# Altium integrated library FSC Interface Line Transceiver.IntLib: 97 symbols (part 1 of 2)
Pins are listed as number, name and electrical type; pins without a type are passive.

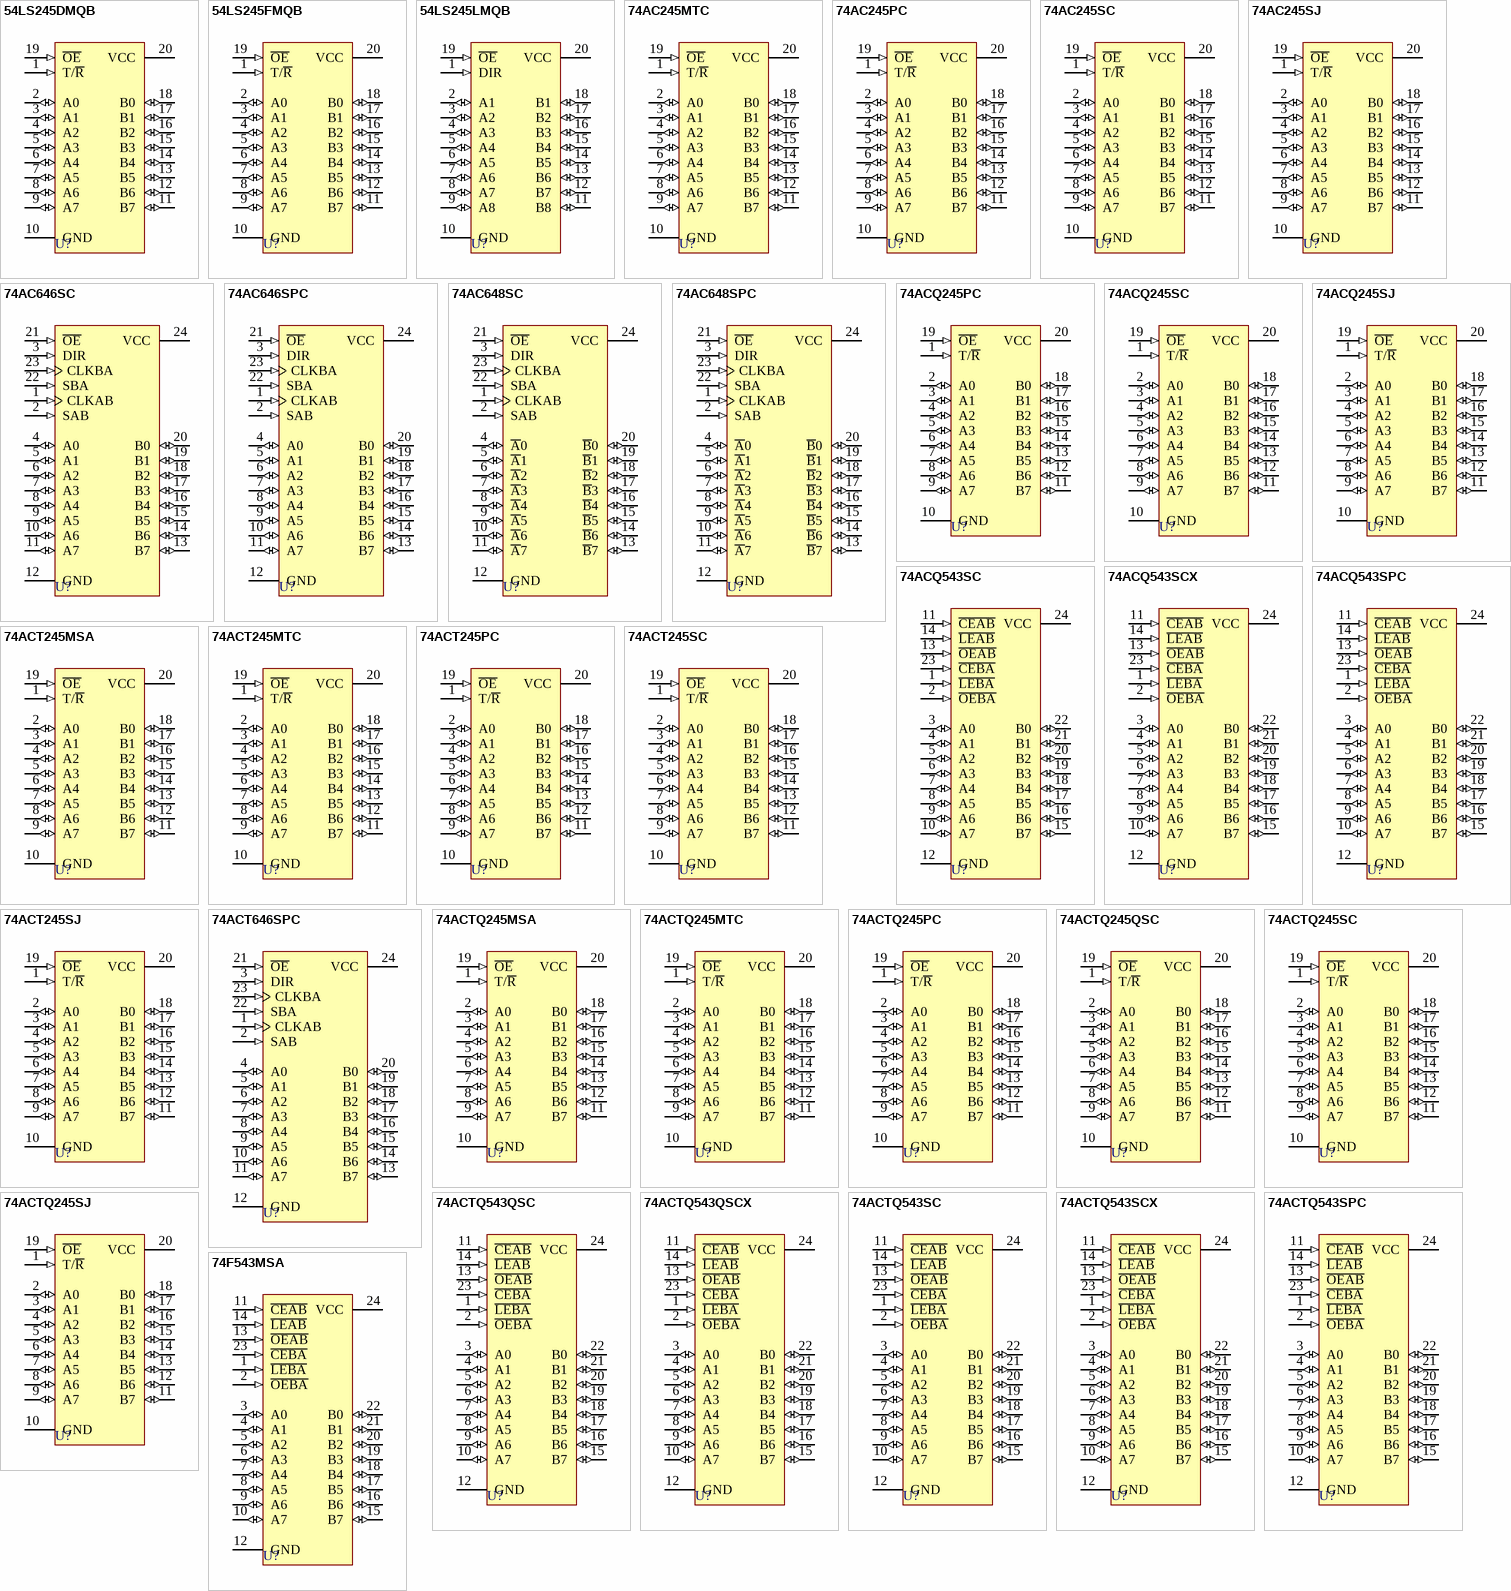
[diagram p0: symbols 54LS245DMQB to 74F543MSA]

## 54LS245DMQB
designator U?
3-State Octal Bus Transceiver
footprint J20A (DIP; 20 Leads; Row Spacing 7.62 mm; Pitch 2.54 mm)
3D model J20A (DIP; 20 Leads; Row Spacing 7.62 mm; Pitch 2.54 mm)
simulation model 74F245 (SIMCODE)
signal-integrity model 54LS245DMQB
pins: 1 T/~{R} (in), 2 A0 (io), 3 A1 (io), 4 A2 (io), 5 A3 (io), 6 A4 (io), 7 A5 (io), 8 A6 (io), 9 A7 (io), 10 GND (power), 11 B7 (io), 12 B6 (io), 13 B5 (io), 14 B4 (io), 15 B3 (io), 16 B2 (io), 17 B1 (io), 18 B0 (io), 19 ~{OE} (in), 20 VCC (power)

## 54LS245FMQB
designator U?
3-State Octal Bus Transceiver
footprint W20A (DFP; 20 Leads; Body 13.7 x 7.2 mm (LxW max); Pitch 1.27 mm)
3D model W20A (DFP; 20 Leads; Body 13.7 x 7.2 mm (LxW max); Pitch 1.27 mm)
simulation model 74F245 (SIMCODE)
signal-integrity model 54LS245FMQB
pins: 1 T/~{R} (in), 2 A0 (io), 3 A1 (io), 4 A2 (io), 5 A3 (io), 6 A4 (io), 7 A5 (io), 8 A6 (io), 9 A7 (io), 10 GND (power), 11 B7 (io), 12 B6 (io), 13 B5 (io), 14 B4 (io), 15 B3 (io), 16 B2 (io), 17 B1 (io), 18 B0 (io), 19 ~{OE} (in), 20 VCC (power)

## 54LS245LMQB
designator U?
3-State Octal Bus Transceiver
footprint E20A (Leadless Chip Carrier; 20 Terminals; Body 8.9 x 8.9 mm)
simulation model 74F245 (SIMCODE)
signal-integrity model 54LS245LMQB
pins: 1 DIR (in), 2 A1 (io), 3 A2 (io), 4 A3 (io), 5 A4 (io), 6 A5 (io), 7 A6 (io), 8 A7 (io), 9 A8 (io), 10 GND (power), 11 B8 (io), 12 B7 (io), 13 B6 (io), 14 B5 (io), 15 B4 (io), 16 B3 (io), 17 B2 (io), 18 B1 (io), 19 ~{OE} (in), 20 VCC (power)

## 74AC245MTC
designator U?
Octal Bidirectional Transceiver with 3-State Input/Output
footprint MTC20 (Shrink Small Outline; 20 Leads; Body Width 4.4 mm; Pitch 0.65 mm)
3D model MTC20 (Shrink Small Outline; 20 Leads; Body Width 4.4 mm; Pitch 0.65 mm)
simulation model 74F245 (SIMCODE)
signal-integrity model 74AC245MTC
pins: 1 T/~{R} (in), 2 A0 (io), 3 A1 (io), 4 A2 (io), 5 A3 (io), 6 A4 (io), 7 A5 (io), 8 A6 (io), 9 A7 (io), 10 GND (power), 11 B7 (io), 12 B6 (io), 13 B5 (io), 14 B4 (io), 15 B3 (io), 16 B2 (io), 17 B1 (io), 18 B0 (io), 19 ~{OE} (in), 20 VCC (power)

## 74AC245PC
designator U?
Octal Bidirectional Transceiver with 3-State Input/Output
footprint N20A (DIP; 20 Leads; Row Spacing 7.62 mm; Pitch 2.54 mm)
3D model N20A (DIP; 20 Leads; Row Spacing 7.62 mm; Pitch 2.54 mm)
simulation model 74F245 (SIMCODE)
signal-integrity model 74AC245PC
pins: 1 T/~{R} (in), 2 A0 (io), 3 A1 (io), 4 A2 (io), 5 A3 (io), 6 A4 (io), 7 A5 (io), 8 A6 (io), 9 A7 (io), 10 GND (power), 11 B7 (io), 12 B6 (io), 13 B5 (io), 14 B4 (io), 15 B3 (io), 16 B2 (io), 17 B1 (io), 18 B0 (io), 19 ~{OE} (in), 20 VCC (power)

## 74AC245SC
designator U?
Octal Bidirectional Transceiver with 3-State Input/Output
footprint M20B_N (SOIC, 20-Leads, Body 12.8x7.5mm, Pitch 1.27mm, IPC Medium Density)
footprint M20B_L (SOIC, 20-Leads, Body 12.8x7.5mm, Pitch 1.27mm, IPC High Density)
footprint M20B_M (SOIC, 20-Leads, Body 12.8x7.5mm, Pitch 1.27mm, IPC Low Density)
3D model M20B (20-Pin Small Outline Integrated Circuit 1.27 mm Pitch)
simulation model 74F245 (SIMCODE)
signal-integrity model 74AC245SC
pins: 1 T/~{R} (in), 2 A0 (io), 3 A1 (io), 4 A2 (io), 5 A3 (io), 6 A4 (io), 7 A5 (io), 8 A6 (io), 9 A7 (io), 10 GND (power), 11 B7 (io), 12 B6 (io), 13 B5 (io), 14 B4 (io), 15 B3 (io), 16 B2 (io), 17 B1 (io), 18 B0 (io), 19 ~{OE} (in), 20 VCC (power)

## 74AC245SJ
designator U?
Octal Bidirectional Transceiver with 3-State Input/Output
footprint M20D_N (SOP, 20-Leads, Body 12.6x5.3mm, Pitch 1.27mm, IPC Medium Density)
footprint M20D_L (SOP, 20-Leads, Body 12.6x5.3mm, Pitch 1.27mm, IPC High Density)
footprint M20D_M (SOP, 20-Leads, Body 12.6x5.3mm, Pitch 1.27mm, IPC Low Density)
3D model M20D (20-Pin Small Outline Package 1.27 mm Pitch)
simulation model 74F245 (SIMCODE)
signal-integrity model 74AC245SJ
pins: 1 T/~{R} (in), 2 A0 (io), 3 A1 (io), 4 A2 (io), 5 A3 (io), 6 A4 (io), 7 A5 (io), 8 A6 (io), 9 A7 (io), 10 GND (power), 11 B7 (io), 12 B6 (io), 13 B5 (io), 14 B4 (io), 15 B3 (io), 16 B2 (io), 17 B1 (io), 18 B0 (io), 19 ~{OE} (in), 20 VCC (power)

## 74AC646SC
designator U?
Octal Transceiver/Register with 3-State Output
footprint M24B_N (SOIC, 24-Leads, Body 15.4x7.5mm, Pitch 1.27mm, IPC Medium Density)
footprint M24B_L (SOIC, 24-Leads, Body 15.4x7.5mm, Pitch 1.27mm, IPC High Density)
footprint M24B_M (SOIC, 24-Leads, Body 15.4x7.5mm, Pitch 1.27mm, IPC Low Density)
3D model M24B (24-Pin Small Outline Integrated Circuit 1.27 mm Pitch)
signal-integrity model 74AC646SC
pins: 1 CLKAB (in), 2 SAB (in), 3 DIR (in), 4 A0 (io), 5 A1 (io), 6 A2 (io), 7 A3 (io), 8 A4 (io), 9 A5 (io), 10 A6 (io), 11 A7 (io), 12 GND (power), 13 B7 (io), 14 B6 (io), 15 B5 (io), 16 B4 (io), 17 B3 (io), 18 B2 (io), 19 B1 (io), 20 B0 (io), 21 ~{OE} (in), 22 SBA (in), 23 CLKBA (in), 24 VCC (power)

## 74AC646SPC
designator U?
Octal Transceiver/Register with 3-State Output
footprint N24C (DIP; 24 Leads; Row Spacing 7.62 mm; Pitch 2.54 mm)
3D model N24C (DIP; 24 Leads; Row Spacing 7.62 mm; Pitch 2.54 mm)
signal-integrity model 74AC646SPC
pins: 1 CLKAB (in), 2 SAB (in), 3 DIR (in), 4 A0 (io), 5 A1 (io), 6 A2 (io), 7 A3 (io), 8 A4 (io), 9 A5 (io), 10 A6 (io), 11 A7 (io), 12 GND (power), 13 B7 (io), 14 B6 (io), 15 B5 (io), 16 B4 (io), 17 B3 (io), 18 B2 (io), 19 B1 (io), 20 B0 (io), 21 ~{OE} (in), 22 SBA (in), 23 CLKBA (in), 24 VCC (power)

## 74AC648SC
designator U?
Octal Transceiver/Register with 3-State Output
footprint M24B_N (SOIC, 24-Leads, Body 15.4x7.5mm, Pitch 1.27mm, IPC Medium Density)
footprint M24B_L (SOIC, 24-Leads, Body 15.4x7.5mm, Pitch 1.27mm, IPC High Density)
footprint M24B_M (SOIC, 24-Leads, Body 15.4x7.5mm, Pitch 1.27mm, IPC Low Density)
3D model M24B (24-Pin Small Outline Integrated Circuit 1.27 mm Pitch)
signal-integrity model 74AC648SC
pins: 1 CLKAB (in), 2 SAB (in), 3 DIR (in), 4 ~{A}0 (io), 5 ~{A}1 (io), 6 ~{A}2 (io), 7 ~{A}3 (io), 8 ~{A}4 (io), 9 ~{A}5 (io), 10 ~{A}6 (io), 11 ~{A}7 (io), 12 GND (power), 13 ~{B}7 (io), 14 ~{B}6 (io), 15 ~{B}5 (io), 16 ~{B}4 (io), 17 ~{B}3 (io), 18 ~{B}2 (io), 19 ~{B}1 (io), 20 ~{B}0 (io), 21 ~{OE} (in), 22 SBA (in), 23 CLKBA (in), 24 VCC (power)

## 74AC648SPC
designator U?
Octal Transceiver/Register with 3-State Output
footprint N24C (DIP; 24 Leads; Row Spacing 7.62 mm; Pitch 2.54 mm)
3D model N24C (DIP; 24 Leads; Row Spacing 7.62 mm; Pitch 2.54 mm)
signal-integrity model 74AC648SPC
pins: 1 CLKAB (in), 2 SAB (in), 3 DIR (in), 4 ~{A}0 (io), 5 ~{A}1 (io), 6 ~{A}2 (io), 7 ~{A}3 (io), 8 ~{A}4 (io), 9 ~{A}5 (io), 10 ~{A}6 (io), 11 ~{A}7 (io), 12 GND (power), 13 ~{B}7 (io), 14 ~{B}6 (io), 15 ~{B}5 (io), 16 ~{B}4 (io), 17 ~{B}3 (io), 18 ~{B}2 (io), 19 ~{B}1 (io), 20 ~{B}0 (io), 21 ~{OE} (in), 22 SBA (in), 23 CLKBA (in), 24 VCC (power)

## 74ACQ245PC
designator U?
Octal Bidirectional Transceiver with 3-State Input/Output
footprint N20A (DIP; 20 Leads; Row Spacing 7.62 mm; Pitch 2.54 mm)
3D model N20A (DIP; 20 Leads; Row Spacing 7.62 mm; Pitch 2.54 mm)
simulation model 74F245 (SIMCODE)
pins: 1 T/~{R} (in), 2 A0 (io), 3 A1 (io), 4 A2 (io), 5 A3 (io), 6 A4 (io), 7 A5 (io), 8 A6 (io), 9 A7 (io), 10 GND (power), 11 B7 (io), 12 B6 (io), 13 B5 (io), 14 B4 (io), 15 B3 (io), 16 B2 (io), 17 B1 (io), 18 B0 (io), 19 ~{OE} (in), 20 VCC (power)

## 74ACQ245SC
designator U?
Octal Bidirectional Transceiver with 3-State Input/Output
footprint M20B_N (SOIC, 20-Leads, Body 12.8x7.5mm, Pitch 1.27mm, IPC Medium Density)
footprint M20B_L (SOIC, 20-Leads, Body 12.8x7.5mm, Pitch 1.27mm, IPC High Density)
footprint M20B_M (SOIC, 20-Leads, Body 12.8x7.5mm, Pitch 1.27mm, IPC Low Density)
3D model M20B (20-Pin Small Outline Integrated Circuit 1.27 mm Pitch)
simulation model 74F245 (SIMCODE)
pins: 1 T/~{R} (in), 2 A0 (io), 3 A1 (io), 4 A2 (io), 5 A3 (io), 6 A4 (io), 7 A5 (io), 8 A6 (io), 9 A7 (io), 10 GND (power), 11 B7 (io), 12 B6 (io), 13 B5 (io), 14 B4 (io), 15 B3 (io), 16 B2 (io), 17 B1 (io), 18 B0 (io), 19 ~{OE} (in), 20 VCC (power)

## 74ACQ245SJ
designator U?
Octal Bidirectional Transceiver with 3-State Input/Output
footprint M20D_N (SOP, 20-Leads, Body 12.6x5.3mm, Pitch 1.27mm, IPC Medium Density)
footprint M20D_L (SOP, 20-Leads, Body 12.6x5.3mm, Pitch 1.27mm, IPC High Density)
footprint M20D_M (SOP, 20-Leads, Body 12.6x5.3mm, Pitch 1.27mm, IPC Low Density)
3D model M20D (20-Pin Small Outline Package 1.27 mm Pitch)
simulation model 74F245 (SIMCODE)
pins: 1 T/~{R} (in), 2 A0 (io), 3 A1 (io), 4 A2 (io), 5 A3 (io), 6 A4 (io), 7 A5 (io), 8 A6 (io), 9 A7 (io), 10 GND (power), 11 B7 (io), 12 B6 (io), 13 B5 (io), 14 B4 (io), 15 B3 (io), 16 B2 (io), 17 B1 (io), 18 B0 (io), 19 ~{OE} (in), 20 VCC (power)

## 74ACQ543SC
designator U?
Octal Registered Transceiver with Tri-State Output
footprint M24B_N (SOIC, 24-Leads, Body 15.4x7.5mm, Pitch 1.27mm, IPC Medium Density)
footprint M24B_L (SOIC, 24-Leads, Body 15.4x7.5mm, Pitch 1.27mm, IPC High Density)
footprint M24B_M (SOIC, 24-Leads, Body 15.4x7.5mm, Pitch 1.27mm, IPC Low Density)
3D model M24B (24-Pin Small Outline Integrated Circuit 1.27 mm Pitch)
pins: 1 ~{LEBA} (in), 2 ~{OEBA} (in), 3 A0 (io), 4 A1 (io), 5 A2 (io), 6 A3 (io), 7 A4 (io), 8 A5 (io), 9 A6 (io), 10 A7 (io), 11 ~{CEAB} (in), 12 GND (power), 13 ~{OEAB} (in), 14 ~{LEAB} (in), 15 B7 (io), 16 B6 (io), 17 B5 (io), 18 B4 (io), 19 B3 (io), 20 B2 (io), 21 B1 (io), 22 B0 (io), 23 ~{CEBA} (in), 24 VCC (power)

## 74ACQ543SCX
designator U?
Octal Registered Transceiver with Tri-State Output
footprint M24B_N (SOIC, 24-Leads, Body 15.4x7.5mm, Pitch 1.27mm, IPC Medium Density)
footprint M24B_L (SOIC, 24-Leads, Body 15.4x7.5mm, Pitch 1.27mm, IPC High Density)
footprint M24B_M (SOIC, 24-Leads, Body 15.4x7.5mm, Pitch 1.27mm, IPC Low Density)
3D model M24B (24-Pin Small Outline Integrated Circuit 1.27 mm Pitch)
pins: 1 ~{LEBA} (in), 2 ~{OEBA} (in), 3 A0 (io), 4 A1 (io), 5 A2 (io), 6 A3 (io), 7 A4 (io), 8 A5 (io), 9 A6 (io), 10 A7 (io), 11 ~{CEAB} (in), 12 GND (power), 13 ~{OEAB} (in), 14 ~{LEAB} (in), 15 B7 (io), 16 B6 (io), 17 B5 (io), 18 B4 (io), 19 B3 (io), 20 B2 (io), 21 B1 (io), 22 B0 (io), 23 ~{CEBA} (in), 24 VCC (power)

## 74ACQ543SPC
designator U?
Octal Registered Transceiver with Tri-State Output
footprint N24C (DIP; 24 Leads; Row Spacing 7.62 mm; Pitch 2.54 mm)
3D model N24C (DIP; 24 Leads; Row Spacing 7.62 mm; Pitch 2.54 mm)
pins: 1 ~{LEBA} (in), 2 ~{OEBA} (in), 3 A0 (io), 4 A1 (io), 5 A2 (io), 6 A3 (io), 7 A4 (io), 8 A5 (io), 9 A6 (io), 10 A7 (io), 11 ~{CEAB} (in), 12 GND (power), 13 ~{OEAB} (in), 14 ~{LEAB} (in), 15 B7 (io), 16 B6 (io), 17 B5 (io), 18 B4 (io), 19 B3 (io), 20 B2 (io), 21 B1 (io), 22 B0 (io), 23 ~{CEBA} (in), 24 VCC (power)

## 74ACT245MSA
designator U?
Octal Bidirectional Transceiver with 3-State Input/Output
footprint MSA20 (SSOP; 20 Leads; Body Width 5.3 mm; Pitch 0.65 mm)
3D model MSA20 (SSOP; 20 Leads; Body Width 5.3 mm; Pitch 0.65 mm)
simulation model 74F245 (SIMCODE)
signal-integrity model 74ACT245MSA
pins: 1 T/~{R} (in), 2 A0 (io), 3 A1 (io), 4 A2 (io), 5 A3 (io), 6 A4 (io), 7 A5 (io), 8 A6 (io), 9 A7 (io), 10 GND (power), 11 B7 (io), 12 B6 (io), 13 B5 (io), 14 B4 (io), 15 B3 (io), 16 B2 (io), 17 B1 (io), 18 B0 (io), 19 ~{OE} (in), 20 VCC (power)

## 74ACT245MTC
designator U?
Octal Bidirectional Transceiver with 3-State Input/Output
footprint MTC20 (Shrink Small Outline; 20 Leads; Body Width 4.4 mm; Pitch 0.65 mm)
3D model MTC20 (Shrink Small Outline; 20 Leads; Body Width 4.4 mm; Pitch 0.65 mm)
simulation model 74F245 (SIMCODE)
signal-integrity model 74ACT245MTC
pins: 1 T/~{R} (in), 2 A0 (io), 3 A1 (io), 4 A2 (io), 5 A3 (io), 6 A4 (io), 7 A5 (io), 8 A6 (io), 9 A7 (io), 10 GND (power), 11 B7 (io), 12 B6 (io), 13 B5 (io), 14 B4 (io), 15 B3 (io), 16 B2 (io), 17 B1 (io), 18 B0 (io), 19 ~{OE} (in), 20 VCC (power)

## 74ACT245PC
designator U?
Octal Bidirectional Transceiver with 3-State Input/Output
footprint N20A (DIP; 20 Leads; Row Spacing 7.62 mm; Pitch 2.54 mm)
3D model N20A (DIP; 20 Leads; Row Spacing 7.62 mm; Pitch 2.54 mm)
simulation model 74F245 (SIMCODE)
signal-integrity model 74ACT245PC
pins: 1 T/~{R} (in), 2 A0 (io), 3 A1 (io), 4 A2 (io), 5 A3 (io), 6 A4 (io), 7 A5 (io), 8 A6 (io), 9 A7 (io), 10 GND (power), 11 B7 (io), 12 B6 (io), 13 B5 (io), 14 B4 (io), 15 B3 (io), 16 B2 (io), 17 B1 (io), 18 B0 (io), 19 ~{OE} (in), 20 VCC (power)

## 74ACT245SC
designator U?
Octal Bidirectional Transceiver with 3-State Input/Output
footprint M20B_N (SOIC, 20-Leads, Body 12.8x7.5mm, Pitch 1.27mm, IPC Medium Density)
footprint M20B_L (SOIC, 20-Leads, Body 12.8x7.5mm, Pitch 1.27mm, IPC High Density)
footprint M20B_M (SOIC, 20-Leads, Body 12.8x7.5mm, Pitch 1.27mm, IPC Low Density)
3D model M20B (20-Pin Small Outline Integrated Circuit 1.27 mm Pitch)
simulation model 74F245 (SIMCODE)
signal-integrity model 74ACT245SC
pins: 1 T/~{R} (in), 2 A0 (io), 3 A1 (io), 4 A2 (io), 5 A3 (io), 6 A4 (io), 7 A5 (io), 8 A6 (io), 9 A7 (io), 10 GND (power), 11 B7 (io), 12 B6 (io), 13 B5 (io), 14 B4 (io), 15 B3 (io), 16 B2 (io), 17 B1 (io), 18 B0 (io), 19 ~{OE} (in), 20 VCC (power)

## 74ACT245SJ
designator U?
Octal Bidirectional Transceiver with 3-State Input/Output
footprint M20D_N (SOP, 20-Leads, Body 12.6x5.3mm, Pitch 1.27mm, IPC Medium Density)
footprint M20D_L (SOP, 20-Leads, Body 12.6x5.3mm, Pitch 1.27mm, IPC High Density)
footprint M20D_M (SOP, 20-Leads, Body 12.6x5.3mm, Pitch 1.27mm, IPC Low Density)
3D model M20D (20-Pin Small Outline Package 1.27 mm Pitch)
simulation model 74F245 (SIMCODE)
signal-integrity model 74ACT245SJ
pins: 1 T/~{R} (in), 2 A0 (io), 3 A1 (io), 4 A2 (io), 5 A3 (io), 6 A4 (io), 7 A5 (io), 8 A6 (io), 9 A7 (io), 10 GND (power), 11 B7 (io), 12 B6 (io), 13 B5 (io), 14 B4 (io), 15 B3 (io), 16 B2 (io), 17 B1 (io), 18 B0 (io), 19 ~{OE} (in), 20 VCC (power)

## 74ACT646SPC
designator U?
Octal Transceiver/Register with 3-State Output
footprint N24C (DIP; 24 Leads; Row Spacing 7.62 mm; Pitch 2.54 mm)
3D model N24C (DIP; 24 Leads; Row Spacing 7.62 mm; Pitch 2.54 mm)
signal-integrity model 74ACT646SPC
pins: 1 CLKAB (in), 2 SAB (in), 3 DIR (in), 4 A0 (io), 5 A1 (io), 6 A2 (io), 7 A3 (io), 8 A4 (io), 9 A5 (io), 10 A6 (io), 11 A7 (io), 12 GND (power), 13 B7 (io), 14 B6 (io), 15 B5 (io), 16 B4 (io), 17 B3 (io), 18 B2 (io), 19 B1 (io), 20 B0 (io), 21 ~{OE} (in), 22 SBA (in), 23 CLKBA (in), 24 VCC (power)

## 74ACTQ245MSA
designator U?
Octal Bidirectional Transceiver with 3-State Input/Output
footprint MSA20 (SSOP; 20 Leads; Body Width 5.3 mm; Pitch 0.65 mm)
3D model MSA20 (SSOP; 20 Leads; Body Width 5.3 mm; Pitch 0.65 mm)
simulation model 74F245 (SIMCODE)
pins: 1 T/~{R} (in), 2 A0 (io), 3 A1 (io), 4 A2 (io), 5 A3 (io), 6 A4 (io), 7 A5 (io), 8 A6 (io), 9 A7 (io), 10 GND (power), 11 B7 (io), 12 B6 (io), 13 B5 (io), 14 B4 (io), 15 B3 (io), 16 B2 (io), 17 B1 (io), 18 B0 (io), 19 ~{OE} (in), 20 VCC (power)

## 74ACTQ245MTC
designator U?
Octal Bidirectional Transceiver with 3-State Input/Output
footprint MTC20 (Shrink Small Outline; 20 Leads; Body Width 4.4 mm; Pitch 0.65 mm)
3D model MTC20 (Shrink Small Outline; 20 Leads; Body Width 4.4 mm; Pitch 0.65 mm)
simulation model 74F245 (SIMCODE)
pins: 1 T/~{R} (in), 2 A0 (io), 3 A1 (io), 4 A2 (io), 5 A3 (io), 6 A4 (io), 7 A5 (io), 8 A6 (io), 9 A7 (io), 10 GND (power), 11 B7 (io), 12 B6 (io), 13 B5 (io), 14 B4 (io), 15 B3 (io), 16 B2 (io), 17 B1 (io), 18 B0 (io), 19 ~{OE} (in), 20 VCC (power)

## 74ACTQ245PC
designator U?
Octal Bidirectional Transceiver with 3-State Input/Output
footprint N20A (DIP; 20 Leads; Row Spacing 7.62 mm; Pitch 2.54 mm)
3D model N20A (DIP; 20 Leads; Row Spacing 7.62 mm; Pitch 2.54 mm)
simulation model 74F245 (SIMCODE)
pins: 1 T/~{R} (in), 2 A0 (io), 3 A1 (io), 4 A2 (io), 5 A3 (io), 6 A4 (io), 7 A5 (io), 8 A6 (io), 9 A7 (io), 10 GND (power), 11 B7 (io), 12 B6 (io), 13 B5 (io), 14 B4 (io), 15 B3 (io), 16 B2 (io), 17 B1 (io), 18 B0 (io), 19 ~{OE} (in), 20 VCC (power)

## 74ACTQ245QSC
designator U?
Octal Bidirectional Transceiver with 3-State Input/Output
footprint MQA20 (SSOP; 20 Leads; Body Width 3.9 mm; Pitch 0.635 mm)
3D model MQA20 (SSOP; 20 Leads; Body Width 3.9 mm; Pitch 0.635 mm)
simulation model 74F245 (SIMCODE)
pins: 1 T/~{R} (in), 2 A0 (io), 3 A1 (io), 4 A2 (io), 5 A3 (io), 6 A4 (io), 7 A5 (io), 8 A6 (io), 9 A7 (io), 10 GND (power), 11 B7 (io), 12 B6 (io), 13 B5 (io), 14 B4 (io), 15 B3 (io), 16 B2 (io), 17 B1 (io), 18 B0 (io), 19 ~{OE} (in), 20 VCC (power)

## 74ACTQ245SC
designator U?
Octal Bidirectional Transceiver with 3-State Input/Output
footprint M20B_N (SOIC, 20-Leads, Body 12.8x7.5mm, Pitch 1.27mm, IPC Medium Density)
footprint M20B_L (SOIC, 20-Leads, Body 12.8x7.5mm, Pitch 1.27mm, IPC High Density)
footprint M20B_M (SOIC, 20-Leads, Body 12.8x7.5mm, Pitch 1.27mm, IPC Low Density)
3D model M20B (20-Pin Small Outline Integrated Circuit 1.27 mm Pitch)
simulation model 74F245 (SIMCODE)
pins: 1 T/~{R} (in), 2 A0 (io), 3 A1 (io), 4 A2 (io), 5 A3 (io), 6 A4 (io), 7 A5 (io), 8 A6 (io), 9 A7 (io), 10 GND (power), 11 B7 (io), 12 B6 (io), 13 B5 (io), 14 B4 (io), 15 B3 (io), 16 B2 (io), 17 B1 (io), 18 B0 (io), 19 ~{OE} (in), 20 VCC (power)

## 74ACTQ245SJ
designator U?
Octal Bidirectional Transceiver with 3-State Input/Output
footprint M20D_N (SOP, 20-Leads, Body 12.6x5.3mm, Pitch 1.27mm, IPC Medium Density)
footprint M20D_L (SOP, 20-Leads, Body 12.6x5.3mm, Pitch 1.27mm, IPC High Density)
footprint M20D_M (SOP, 20-Leads, Body 12.6x5.3mm, Pitch 1.27mm, IPC Low Density)
3D model M20D (20-Pin Small Outline Package 1.27 mm Pitch)
simulation model 74F245 (SIMCODE)
pins: 1 T/~{R} (in), 2 A0 (io), 3 A1 (io), 4 A2 (io), 5 A3 (io), 6 A4 (io), 7 A5 (io), 8 A6 (io), 9 A7 (io), 10 GND (power), 11 B7 (io), 12 B6 (io), 13 B5 (io), 14 B4 (io), 15 B3 (io), 16 B2 (io), 17 B1 (io), 18 B0 (io), 19 ~{OE} (in), 20 VCC (power)

## 74ACTQ543QSC
designator U?
Octal Registered Transceiver with Tri-State Output
footprint MQA24 (SSOP; 24 Leads; Body Width 3.9 mm; Pitch 0.635 mm)
3D model MQA24 (SSOP; 24 Leads; Body Width 3.9 mm; Pitch 0.635 mm)
pins: 1 ~{LEBA} (in), 2 ~{OEBA} (in), 3 A0 (io), 4 A1 (io), 5 A2 (io), 6 A3 (io), 7 A4 (io), 8 A5 (io), 9 A6 (io), 10 A7 (io), 11 ~{CEAB} (in), 12 GND (power), 13 ~{OEAB} (in), 14 ~{LEAB} (in), 15 B7 (io), 16 B6 (io), 17 B5 (io), 18 B4 (io), 19 B3 (io), 20 B2 (io), 21 B1 (io), 22 B0 (io), 23 ~{CEBA} (in), 24 VCC (power)

## 74ACTQ543QSCX
designator U?
Octal Registered Transceiver with Tri-State Output
footprint MQA24 (SSOP; 24 Leads; Body Width 3.9 mm; Pitch 0.635 mm)
3D model MQA24 (SSOP; 24 Leads; Body Width 3.9 mm; Pitch 0.635 mm)
pins: 1 ~{LEBA} (in), 2 ~{OEBA} (in), 3 A0 (io), 4 A1 (io), 5 A2 (io), 6 A3 (io), 7 A4 (io), 8 A5 (io), 9 A6 (io), 10 A7 (io), 11 ~{CEAB} (in), 12 GND (power), 13 ~{OEAB} (in), 14 ~{LEAB} (in), 15 B7 (io), 16 B6 (io), 17 B5 (io), 18 B4 (io), 19 B3 (io), 20 B2 (io), 21 B1 (io), 22 B0 (io), 23 ~{CEBA} (in), 24 VCC (power)

## 74ACTQ543SC
designator U?
Octal Registered Transceiver with Tri-State Output
footprint M24B_N (SOIC, 24-Leads, Body 15.4x7.5mm, Pitch 1.27mm, IPC Medium Density)
footprint M24B_L (SOIC, 24-Leads, Body 15.4x7.5mm, Pitch 1.27mm, IPC High Density)
footprint M24B_M (SOIC, 24-Leads, Body 15.4x7.5mm, Pitch 1.27mm, IPC Low Density)
3D model M24B (24-Pin Small Outline Integrated Circuit 1.27 mm Pitch)
pins: 1 ~{LEBA} (in), 2 ~{OEBA} (in), 3 A0 (io), 4 A1 (io), 5 A2 (io), 6 A3 (io), 7 A4 (io), 8 A5 (io), 9 A6 (io), 10 A7 (io), 11 ~{CEAB} (in), 12 GND (power), 13 ~{OEAB} (in), 14 ~{LEAB} (in), 15 B7 (io), 16 B6 (io), 17 B5 (io), 18 B4 (io), 19 B3 (io), 20 B2 (io), 21 B1 (io), 22 B0 (io), 23 ~{CEBA} (in), 24 VCC (power)

## 74ACTQ543SCX
designator U?
Octal Registered Transceiver with Tri-State Output
footprint M24B_N (SOIC, 24-Leads, Body 15.4x7.5mm, Pitch 1.27mm, IPC Medium Density)
footprint M24B_L (SOIC, 24-Leads, Body 15.4x7.5mm, Pitch 1.27mm, IPC High Density)
footprint M24B_M (SOIC, 24-Leads, Body 15.4x7.5mm, Pitch 1.27mm, IPC Low Density)
3D model M24B (24-Pin Small Outline Integrated Circuit 1.27 mm Pitch)
pins: 1 ~{LEBA} (in), 2 ~{OEBA} (in), 3 A0 (io), 4 A1 (io), 5 A2 (io), 6 A3 (io), 7 A4 (io), 8 A5 (io), 9 A6 (io), 10 A7 (io), 11 ~{CEAB} (in), 12 GND (power), 13 ~{OEAB} (in), 14 ~{LEAB} (in), 15 B7 (io), 16 B6 (io), 17 B5 (io), 18 B4 (io), 19 B3 (io), 20 B2 (io), 21 B1 (io), 22 B0 (io), 23 ~{CEBA} (in), 24 VCC (power)

## 74ACTQ543SPC
designator U?
Octal Registered Transceiver with Tri-State Output
footprint N24C (DIP; 24 Leads; Row Spacing 7.62 mm; Pitch 2.54 mm)
3D model N24C (DIP; 24 Leads; Row Spacing 7.62 mm; Pitch 2.54 mm)
pins: 1 ~{LEBA} (in), 2 ~{OEBA} (in), 3 A0 (io), 4 A1 (io), 5 A2 (io), 6 A3 (io), 7 A4 (io), 8 A5 (io), 9 A6 (io), 10 A7 (io), 11 ~{CEAB} (in), 12 GND (power), 13 ~{OEAB} (in), 14 ~{LEAB} (in), 15 B7 (io), 16 B6 (io), 17 B5 (io), 18 B4 (io), 19 B3 (io), 20 B2 (io), 21 B1 (io), 22 B0 (io), 23 ~{CEBA} (in), 24 VCC (power)

## 74F543MSA
designator U?
Octal Registered Transceiver
footprint MSA24 (SSOP; 24 Leads; Body Width 5.3 mm; Pitch 0.65 mm)
3D model MSA24 (SSOP; 24 Leads; Body Width 5.3 mm; Pitch 0.65 mm)
signal-integrity model 74F543MSA
pins: 1 ~{LEBA} (in), 2 ~{OEBA} (in), 3 A0 (io), 4 A1 (io), 5 A2 (io), 6 A3 (io), 7 A4 (io), 8 A5 (io), 9 A6 (io), 10 A7 (io), 11 ~{CEAB} (in), 12 GND (power), 13 ~{OEAB} (in), 14 ~{LEAB} (in), 15 B7 (io), 16 B6 (io), 17 B5 (io), 18 B4 (io), 19 B3 (io), 20 B2 (io), 21 B1 (io), 22 B0 (io), 23 ~{CEBA} (in), 24 VCC (power)

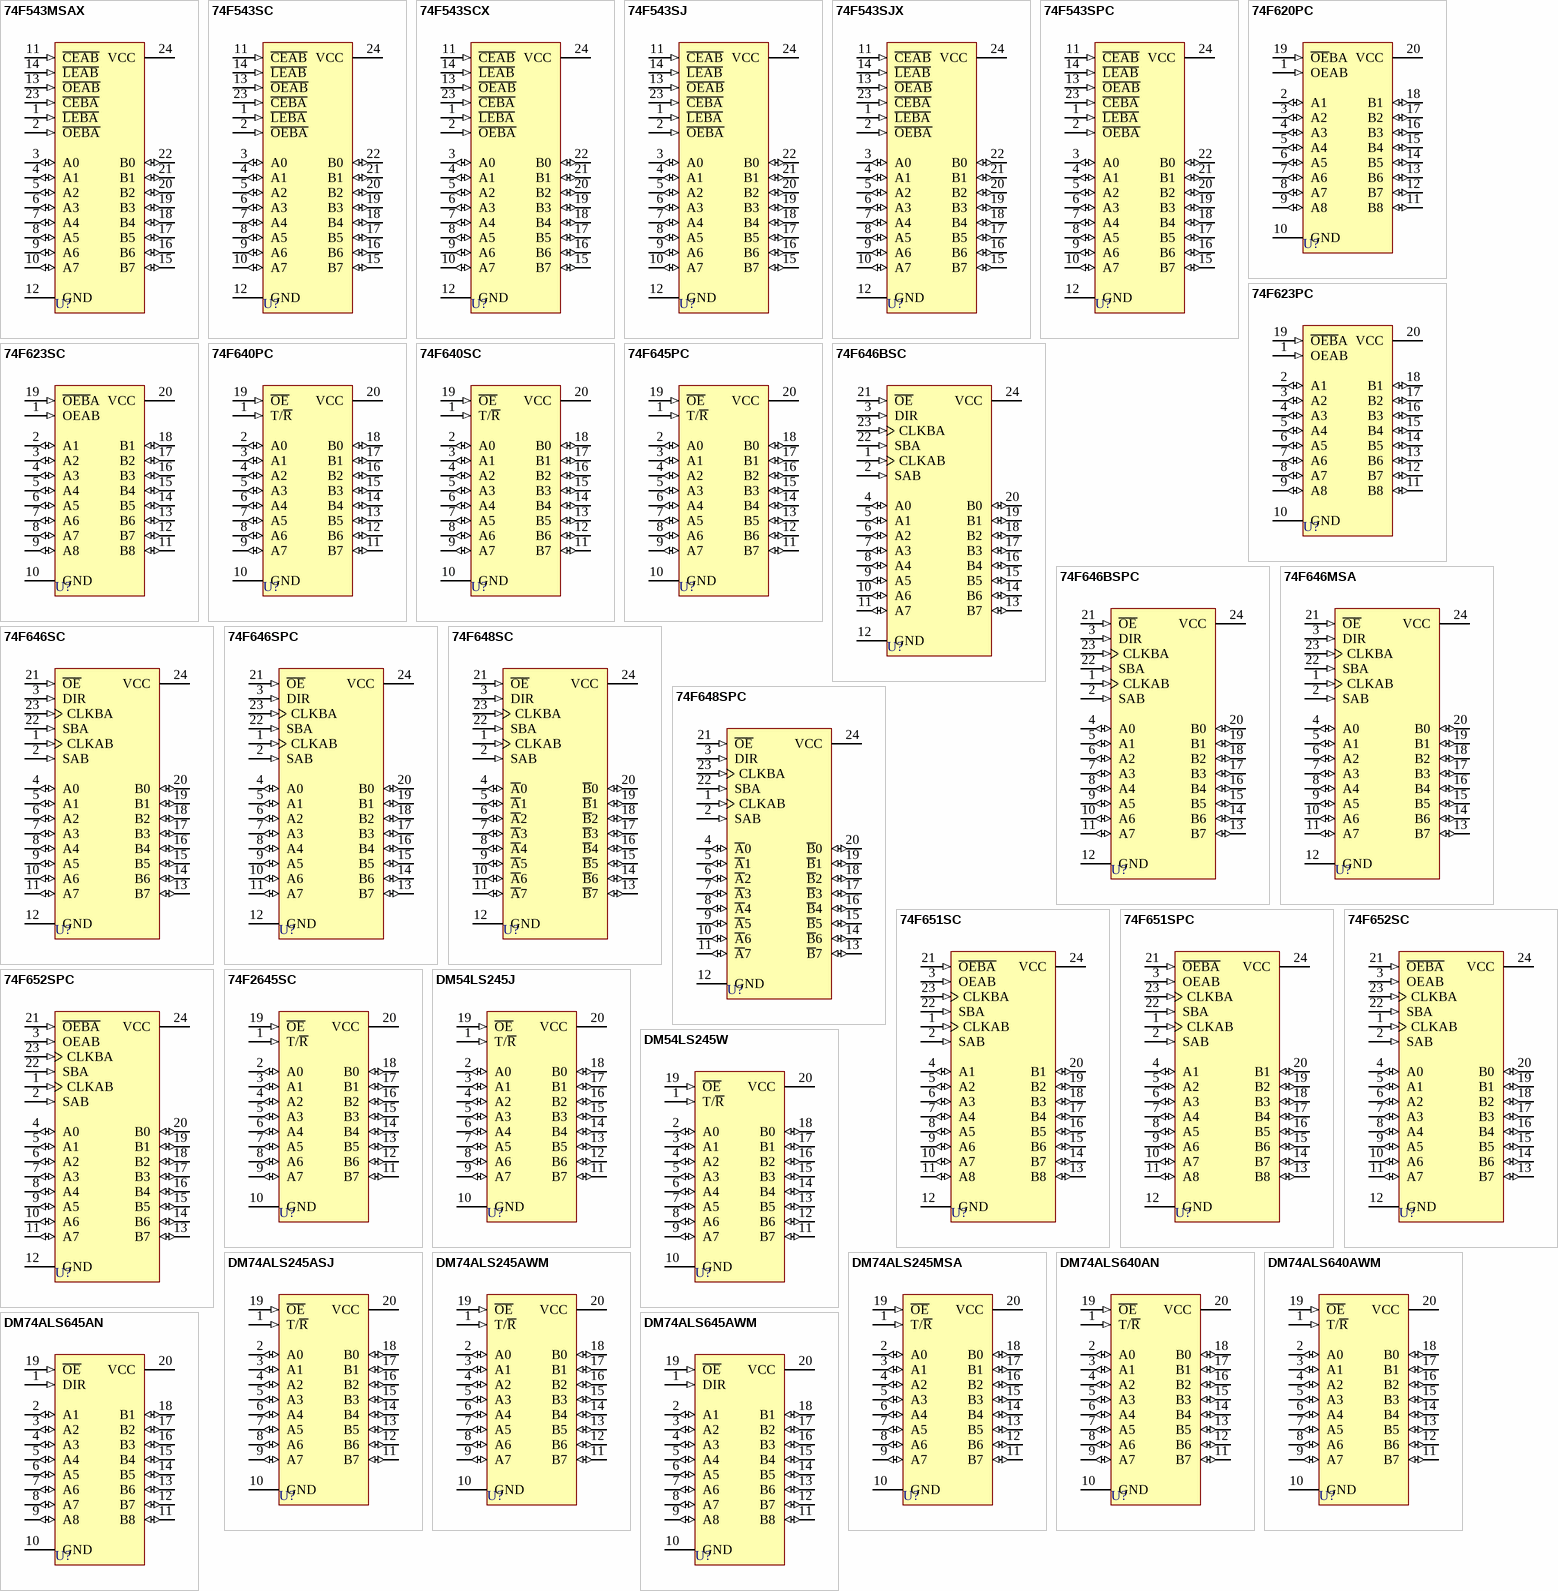
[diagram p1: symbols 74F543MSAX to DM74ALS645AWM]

## 74F543MSAX
designator U?
Octal Registered Transceiver
footprint MSA24 (SSOP; 24 Leads; Body Width 5.3 mm; Pitch 0.65 mm)
3D model MSA24 (SSOP; 24 Leads; Body Width 5.3 mm; Pitch 0.65 mm)
signal-integrity model 74F543MSAX
pins: 1 ~{LEBA} (in), 2 ~{OEBA} (in), 3 A0 (io), 4 A1 (io), 5 A2 (io), 6 A3 (io), 7 A4 (io), 8 A5 (io), 9 A6 (io), 10 A7 (io), 11 ~{CEAB} (in), 12 GND (power), 13 ~{OEAB} (in), 14 ~{LEAB} (in), 15 B7 (io), 16 B6 (io), 17 B5 (io), 18 B4 (io), 19 B3 (io), 20 B2 (io), 21 B1 (io), 22 B0 (io), 23 ~{CEBA} (in), 24 VCC (power)

## 74F543SC
designator U?
Octal Registered Transceiver
footprint M24B_N (SOIC, 24-Leads, Body 15.4x7.5mm, Pitch 1.27mm, IPC Medium Density)
footprint M24B_L (SOIC, 24-Leads, Body 15.4x7.5mm, Pitch 1.27mm, IPC High Density)
footprint M24B_M (SOIC, 24-Leads, Body 15.4x7.5mm, Pitch 1.27mm, IPC Low Density)
3D model M24B (24-Pin Small Outline Integrated Circuit 1.27 mm Pitch)
signal-integrity model 74F543SC
pins: 1 ~{LEBA} (in), 2 ~{OEBA} (in), 3 A0 (io), 4 A1 (io), 5 A2 (io), 6 A3 (io), 7 A4 (io), 8 A5 (io), 9 A6 (io), 10 A7 (io), 11 ~{CEAB} (in), 12 GND (power), 13 ~{OEAB} (in), 14 ~{LEAB} (in), 15 B7 (io), 16 B6 (io), 17 B5 (io), 18 B4 (io), 19 B3 (io), 20 B2 (io), 21 B1 (io), 22 B0 (io), 23 ~{CEBA} (in), 24 VCC (power)

## 74F543SCX
designator U?
Octal Registered Transceiver
footprint M24B_N (SOIC, 24-Leads, Body 15.4x7.5mm, Pitch 1.27mm, IPC Medium Density)
footprint M24B_L (SOIC, 24-Leads, Body 15.4x7.5mm, Pitch 1.27mm, IPC High Density)
footprint M24B_M (SOIC, 24-Leads, Body 15.4x7.5mm, Pitch 1.27mm, IPC Low Density)
3D model M24B (24-Pin Small Outline Integrated Circuit 1.27 mm Pitch)
signal-integrity model 74F543SCX
pins: 1 ~{LEBA} (in), 2 ~{OEBA} (in), 3 A0 (io), 4 A1 (io), 5 A2 (io), 6 A3 (io), 7 A4 (io), 8 A5 (io), 9 A6 (io), 10 A7 (io), 11 ~{CEAB} (in), 12 GND (power), 13 ~{OEAB} (in), 14 ~{LEAB} (in), 15 B7 (io), 16 B6 (io), 17 B5 (io), 18 B4 (io), 19 B3 (io), 20 B2 (io), 21 B1 (io), 22 B0 (io), 23 ~{CEBA} (in), 24 VCC (power)

## 74F543SJ
designator U?
Octal Registered Transceiver
footprint M24B_N (SOIC, 24-Leads, Body 15.4x7.5mm, Pitch 1.27mm, IPC Medium Density)
footprint M24B_L (SOIC, 24-Leads, Body 15.4x7.5mm, Pitch 1.27mm, IPC High Density)
footprint M24B_M (SOIC, 24-Leads, Body 15.4x7.5mm, Pitch 1.27mm, IPC Low Density)
3D model M24B (24-Pin Small Outline Integrated Circuit 1.27 mm Pitch)
signal-integrity model 74F543SJ
pins: 1 ~{LEBA} (in), 2 ~{OEBA} (in), 3 A0 (io), 4 A1 (io), 5 A2 (io), 6 A3 (io), 7 A4 (io), 8 A5 (io), 9 A6 (io), 10 A7 (io), 11 ~{CEAB} (in), 12 GND (power), 13 ~{OEAB} (in), 14 ~{LEAB} (in), 15 B7 (io), 16 B6 (io), 17 B5 (io), 18 B4 (io), 19 B3 (io), 20 B2 (io), 21 B1 (io), 22 B0 (io), 23 ~{CEBA} (in), 24 VCC (power)

## 74F543SJX
designator U?
Octal Registered Transceiver
footprint M24B_N (SOIC, 24-Leads, Body 15.4x7.5mm, Pitch 1.27mm, IPC Medium Density)
footprint M24B_L (SOIC, 24-Leads, Body 15.4x7.5mm, Pitch 1.27mm, IPC High Density)
footprint M24B_M (SOIC, 24-Leads, Body 15.4x7.5mm, Pitch 1.27mm, IPC Low Density)
3D model M24B (24-Pin Small Outline Integrated Circuit 1.27 mm Pitch)
signal-integrity model 74F543SJX
pins: 1 ~{LEBA} (in), 2 ~{OEBA} (in), 3 A0 (io), 4 A1 (io), 5 A2 (io), 6 A3 (io), 7 A4 (io), 8 A5 (io), 9 A6 (io), 10 A7 (io), 11 ~{CEAB} (in), 12 GND (power), 13 ~{OEAB} (in), 14 ~{LEAB} (in), 15 B7 (io), 16 B6 (io), 17 B5 (io), 18 B4 (io), 19 B3 (io), 20 B2 (io), 21 B1 (io), 22 B0 (io), 23 ~{CEBA} (in), 24 VCC (power)

## 74F543SPC
designator U?
Octal Registered Transceiver
footprint N24C (DIP; 24 Leads; Row Spacing 7.62 mm; Pitch 2.54 mm)
3D model N24C (DIP; 24 Leads; Row Spacing 7.62 mm; Pitch 2.54 mm)
signal-integrity model 74F543SPC
pins: 1 ~{LEBA} (in), 2 ~{OEBA} (in), 3 A0 (io), 4 A1 (io), 5 A2 (io), 6 A3 (io), 7 A4 (io), 8 A5 (io), 9 A6 (io), 10 A7 (io), 11 ~{CEAB} (in), 12 GND (power), 13 ~{OEAB} (in), 14 ~{LEAB} (in), 15 B7 (io), 16 B6 (io), 17 B5 (io), 18 B4 (io), 19 B3 (io), 20 B2 (io), 21 B1 (io), 22 B0 (io), 23 ~{CEBA} (in), 24 VCC (power)

## 74F620PC
designator U?
Inverting Octal Bus Transceiver with 3-State Output
footprint N20A (DIP; 20 Leads; Row Spacing 7.62 mm; Pitch 2.54 mm)
3D model N20A (DIP; 20 Leads; Row Spacing 7.62 mm; Pitch 2.54 mm)
signal-integrity model 74F620PC
pins: 1 OEAB (in), 2 A1 (io), 3 A2 (io), 4 A3 (io), 5 A4 (io), 6 A5 (io), 7 A6 (io), 8 A7 (io), 9 A8 (io), 10 GND (power), 11 B8 (io), 12 B7 (io), 13 B6 (io), 14 B5 (io), 15 B4 (io), 16 B3 (io), 17 B2 (io), 18 B1 (io), 19 ~{OE}BA (in), 20 VCC (power)

## 74F623PC
designator U?
Inverting Octal Bus Transceiver with 3-State Output
footprint N20A (DIP; 20 Leads; Row Spacing 7.62 mm; Pitch 2.54 mm)
3D model N20A (DIP; 20 Leads; Row Spacing 7.62 mm; Pitch 2.54 mm)
signal-integrity model 74F623PC
pins: 1 OEAB (in), 2 A1 (io), 3 A2 (io), 4 A3 (io), 5 A4 (io), 6 A5 (io), 7 A6 (io), 8 A7 (io), 9 A8 (io), 10 GND (power), 11 B8 (io), 12 B7 (io), 13 B6 (io), 14 B5 (io), 15 B4 (io), 16 B3 (io), 17 B2 (io), 18 B1 (io), 19 ~{OEB}A (in), 20 VCC (power)

## 74F623SC
designator U?
Inverting Octal Bus Transceiver with 3-State Output
footprint M20B_N (SOIC, 20-Leads, Body 12.8x7.5mm, Pitch 1.27mm, IPC Medium Density)
footprint M20B_L (SOIC, 20-Leads, Body 12.8x7.5mm, Pitch 1.27mm, IPC High Density)
footprint M20B_M (SOIC, 20-Leads, Body 12.8x7.5mm, Pitch 1.27mm, IPC Low Density)
3D model M20B (20-Pin Small Outline Integrated Circuit 1.27 mm Pitch)
signal-integrity model 74F623SC
pins: 1 OEAB (in), 2 A1 (io), 3 A2 (io), 4 A3 (io), 5 A4 (io), 6 A5 (io), 7 A6 (io), 8 A7 (io), 9 A8 (io), 10 GND (power), 11 B8 (io), 12 B7 (io), 13 B6 (io), 14 B5 (io), 15 B4 (io), 16 B3 (io), 17 B2 (io), 18 B1 (io), 19 ~{OEB}A (in), 20 VCC (power)

## 74F640PC
designator U?
Octal Bus Transceiver with 3-State Output
footprint N20A (DIP; 20 Leads; Row Spacing 7.62 mm; Pitch 2.54 mm)
3D model N20A (DIP; 20 Leads; Row Spacing 7.62 mm; Pitch 2.54 mm)
signal-integrity model 74F640PC
pins: 1 T/~{R} (in), 2 A0 (io), 3 A1 (io), 4 A2 (io), 5 A3 (io), 6 A4 (io), 7 A5 (io), 8 A6 (io), 9 A7 (io), 10 GND (power), 11 B7 (io), 12 B6 (io), 13 B5 (io), 14 B4 (io), 15 B3 (io), 16 B2 (io), 17 B1 (io), 18 B0 (io), 19 ~{OE} (in), 20 VCC (power)

## 74F640SC
designator U?
Octal Bus Transceiver with 3-State Output
footprint M20B_N (SOIC, 20-Leads, Body 12.8x7.5mm, Pitch 1.27mm, IPC Medium Density)
footprint M20B_L (SOIC, 20-Leads, Body 12.8x7.5mm, Pitch 1.27mm, IPC High Density)
footprint M20B_M (SOIC, 20-Leads, Body 12.8x7.5mm, Pitch 1.27mm, IPC Low Density)
3D model M20B (20-Pin Small Outline Integrated Circuit 1.27 mm Pitch)
signal-integrity model 74F640SC
pins: 1 T/~{R} (in), 2 A0 (io), 3 A1 (io), 4 A2 (io), 5 A3 (io), 6 A4 (io), 7 A5 (io), 8 A6 (io), 9 A7 (io), 10 GND (power), 11 B7 (io), 12 B6 (io), 13 B5 (io), 14 B4 (io), 15 B3 (io), 16 B2 (io), 17 B1 (io), 18 B0 (io), 19 ~{OE} (in), 20 VCC (power)

## 74F645PC
designator U?
Octal Bus Transceiver with 3-State Output
footprint N20A (DIP; 20 Leads; Row Spacing 7.62 mm; Pitch 2.54 mm)
3D model N20A (DIP; 20 Leads; Row Spacing 7.62 mm; Pitch 2.54 mm)
signal-integrity model 74F645PC
pins: 1 T/~{R} (in), 2 A0 (io), 3 A1 (io), 4 A2 (io), 5 A3 (io), 6 A4 (io), 7 A5 (io), 8 A6 (io), 9 A7 (io), 10 GND (power), 11 B7 (io), 12 B6 (io), 13 B5 (io), 14 B4 (io), 15 B3 (io), 16 B2 (io), 17 B1 (io), 18 B0 (io), 19 ~{OE} (in), 20 VCC (power)

## 74F646BSC
designator U?
Octal Transceiver/Register with 3-State Output
footprint M24B_N (SOIC, 24-Leads, Body 15.4x7.5mm, Pitch 1.27mm, IPC Medium Density)
footprint M24B_L (SOIC, 24-Leads, Body 15.4x7.5mm, Pitch 1.27mm, IPC High Density)
footprint M24B_M (SOIC, 24-Leads, Body 15.4x7.5mm, Pitch 1.27mm, IPC Low Density)
3D model M24B (24-Pin Small Outline Integrated Circuit 1.27 mm Pitch)
signal-integrity model 74F646BSC
pins: 1 CLKAB (in), 2 SAB (in), 3 DIR (in), 4 A0 (io), 5 A1 (io), 6 A2 (io), 7 A3 (io), 8 A4 (io), 9 A5 (io), 10 A6 (io), 11 A7 (io), 12 GND (power), 13 B7 (io), 14 B6 (io), 15 B5 (io), 16 B4 (io), 17 B3 (io), 18 B2 (io), 19 B1 (io), 20 B0 (io), 21 ~{OE} (in), 22 SBA (in), 23 CLKBA (in), 24 VCC (power)

## 74F646BSPC
designator U?
Octal Transceiver/Register with 3-State Output
footprint N24C (DIP; 24 Leads; Row Spacing 7.62 mm; Pitch 2.54 mm)
3D model N24C (DIP; 24 Leads; Row Spacing 7.62 mm; Pitch 2.54 mm)
signal-integrity model 74F646BSPC
pins: 1 CLKAB (in), 2 SAB (in), 3 DIR (in), 4 A0 (io), 5 A1 (io), 6 A2 (io), 7 A3 (io), 8 A4 (io), 9 A5 (io), 10 A6 (io), 11 A7 (io), 12 GND (power), 13 B7 (io), 14 B6 (io), 15 B5 (io), 16 B4 (io), 17 B3 (io), 18 B2 (io), 19 B1 (io), 20 B0 (io), 21 ~{OE} (in), 22 SBA (in), 23 CLKBA (in), 24 VCC (power)

## 74F646MSA
designator U?
Octal Transceiver/Register with 3-State Output
footprint MSA24 (SSOP; 24 Leads; Body Width 5.3 mm; Pitch 0.65 mm)
3D model MSA24 (SSOP; 24 Leads; Body Width 5.3 mm; Pitch 0.65 mm)
signal-integrity model 74F646MSA
pins: 1 CLKAB (in), 2 SAB (in), 3 DIR (in), 4 A0 (io), 5 A1 (io), 6 A2 (io), 7 A3 (io), 8 A4 (io), 9 A5 (io), 10 A6 (io), 11 A7 (io), 12 GND (power), 13 B7 (io), 14 B6 (io), 15 B5 (io), 16 B4 (io), 17 B3 (io), 18 B2 (io), 19 B1 (io), 20 B0 (io), 21 ~{OE} (in), 22 SBA (in), 23 CLKBA (in), 24 VCC (power)

## 74F646SC
designator U?
Octal Transceiver/Register with 3-State Output
footprint M24B_N (SOIC, 24-Leads, Body 15.4x7.5mm, Pitch 1.27mm, IPC Medium Density)
footprint M24B_L (SOIC, 24-Leads, Body 15.4x7.5mm, Pitch 1.27mm, IPC High Density)
footprint M24B_M (SOIC, 24-Leads, Body 15.4x7.5mm, Pitch 1.27mm, IPC Low Density)
3D model M24B (24-Pin Small Outline Integrated Circuit 1.27 mm Pitch)
signal-integrity model 74F646SC
pins: 1 CLKAB (in), 2 SAB (in), 3 DIR (in), 4 A0 (io), 5 A1 (io), 6 A2 (io), 7 A3 (io), 8 A4 (io), 9 A5 (io), 10 A6 (io), 11 A7 (io), 12 GND (power), 13 B7 (io), 14 B6 (io), 15 B5 (io), 16 B4 (io), 17 B3 (io), 18 B2 (io), 19 B1 (io), 20 B0 (io), 21 ~{OE} (in), 22 SBA (in), 23 CLKBA (in), 24 VCC (power)

## 74F646SPC
designator U?
Octal Transceiver/Register with 3-State Output
footprint N24C (DIP; 24 Leads; Row Spacing 7.62 mm; Pitch 2.54 mm)
3D model N24C (DIP; 24 Leads; Row Spacing 7.62 mm; Pitch 2.54 mm)
signal-integrity model 74F646SPC
pins: 1 CLKAB (in), 2 SAB (in), 3 DIR (in), 4 A0 (io), 5 A1 (io), 6 A2 (io), 7 A3 (io), 8 A4 (io), 9 A5 (io), 10 A6 (io), 11 A7 (io), 12 GND (power), 13 B7 (io), 14 B6 (io), 15 B5 (io), 16 B4 (io), 17 B3 (io), 18 B2 (io), 19 B1 (io), 20 B0 (io), 21 ~{OE} (in), 22 SBA (in), 23 CLKBA (in), 24 VCC (power)

## 74F648SC
designator U?
Octal Transceiver/Register with 3-State Output
footprint M24B_N (SOIC, 24-Leads, Body 15.4x7.5mm, Pitch 1.27mm, IPC Medium Density)
footprint M24B_L (SOIC, 24-Leads, Body 15.4x7.5mm, Pitch 1.27mm, IPC High Density)
footprint M24B_M (SOIC, 24-Leads, Body 15.4x7.5mm, Pitch 1.27mm, IPC Low Density)
3D model M24B (24-Pin Small Outline Integrated Circuit 1.27 mm Pitch)
signal-integrity model 74F648SC
pins: 1 CLKAB (in), 2 SAB (in), 3 DIR (in), 4 ~{A}0 (io), 5 ~{A}1 (io), 6 ~{A}2 (io), 7 ~{A}3 (io), 8 ~{A}4 (io), 9 ~{A}5 (io), 10 ~{A}6 (io), 11 ~{A}7 (io), 12 GND (power), 13 ~{B}7 (io), 14 ~{B}6 (io), 15 ~{B}5 (io), 16 ~{B}4 (io), 17 ~{B}3 (io), 18 ~{B}2 (io), 19 ~{B}1 (io), 20 ~{B}0 (io), 21 ~{OE} (in), 22 SBA (in), 23 CLKBA (in), 24 VCC (power)

## 74F648SPC
designator U?
Octal Transceiver/Register with 3-State Output
footprint N24C (DIP; 24 Leads; Row Spacing 7.62 mm; Pitch 2.54 mm)
3D model N24C (DIP; 24 Leads; Row Spacing 7.62 mm; Pitch 2.54 mm)
signal-integrity model 74F648SPC
pins: 1 CLKAB (in), 2 SAB (in), 3 DIR (in), 4 ~{A}0 (io), 5 ~{A}1 (io), 6 ~{A}2 (io), 7 ~{A}3 (io), 8 ~{A}4 (io), 9 ~{A}5 (io), 10 ~{A}6 (io), 11 ~{A}7 (io), 12 GND (power), 13 ~{B}7 (io), 14 ~{B}6 (io), 15 ~{B}5 (io), 16 ~{B}4 (io), 17 ~{B}3 (io), 18 ~{B}2 (io), 19 ~{B}1 (io), 20 ~{B}0 (io), 21 ~{OE} (in), 22 SBA (in), 23 CLKBA (in), 24 VCC (power)

## 74F651SC
designator U?
Transceiver/Register
footprint M24B_N (SOIC, 24-Leads, Body 15.4x7.5mm, Pitch 1.27mm, IPC Medium Density)
footprint M24B_L (SOIC, 24-Leads, Body 15.4x7.5mm, Pitch 1.27mm, IPC High Density)
footprint M24B_M (SOIC, 24-Leads, Body 15.4x7.5mm, Pitch 1.27mm, IPC Low Density)
3D model M24B (24-Pin Small Outline Integrated Circuit 1.27 mm Pitch)
signal-integrity model 74F651SC
pins: 1 CLKAB (in), 2 SAB (in), 3 OEAB (in), 4 A1 (io), 5 A2 (io), 6 A3 (io), 7 A4 (io), 8 A5 (io), 9 A6 (io), 10 A7 (io), 11 A8 (io), 12 GND (power), 13 B8 (io), 14 B7 (io), 15 B6 (io), 16 B5 (io), 17 B4 (io), 18 B3 (io), 19 B2 (io), 20 B1 (io), 21 ~{OEBA} (in), 22 SBA (in), 23 CLKBA (in), 24 VCC (power)

## 74F651SPC
designator U?
Transceiver/Register
footprint N24C (DIP; 24 Leads; Row Spacing 7.62 mm; Pitch 2.54 mm)
3D model N24C (DIP; 24 Leads; Row Spacing 7.62 mm; Pitch 2.54 mm)
signal-integrity model 74F651SPC
pins: 1 CLKAB (in), 2 SAB (in), 3 OEAB (in), 4 A1 (io), 5 A2 (io), 6 A3 (io), 7 A4 (io), 8 A5 (io), 9 A6 (io), 10 A7 (io), 11 A8 (io), 12 GND (power), 13 B8 (io), 14 B7 (io), 15 B6 (io), 16 B5 (io), 17 B4 (io), 18 B3 (io), 19 B2 (io), 20 B1 (io), 21 ~{OEBA} (in), 22 SBA (in), 23 CLKBA (in), 24 VCC (power)

## 74F652SC
designator U?
Transceiver/Register
footprint M24B_N (SOIC, 24-Leads, Body 15.4x7.5mm, Pitch 1.27mm, IPC Medium Density)
footprint M24B_L (SOIC, 24-Leads, Body 15.4x7.5mm, Pitch 1.27mm, IPC High Density)
footprint M24B_M (SOIC, 24-Leads, Body 15.4x7.5mm, Pitch 1.27mm, IPC Low Density)
3D model M24B (24-Pin Small Outline Integrated Circuit 1.27 mm Pitch)
signal-integrity model 74F652SC
pins: 1 CLKAB (in), 2 SAB (in), 3 OEAB (in), 4 A0 (io), 5 A1 (io), 6 A2 (io), 7 A3 (io), 8 A4 (io), 9 A5 (io), 10 A6 (io), 11 A7 (io), 12 GND (power), 13 B7 (io), 14 B6 (io), 15 B5 (io), 16 B4 (io), 17 B3 (io), 18 B2 (io), 19 B1 (io), 20 B0 (io), 21 ~{OEBA} (in), 22 SBA (in), 23 CLKBA (in), 24 VCC (power)

## 74F652SPC
designator U?
Transceiver/Register
footprint N24C (DIP; 24 Leads; Row Spacing 7.62 mm; Pitch 2.54 mm)
3D model N24C (DIP; 24 Leads; Row Spacing 7.62 mm; Pitch 2.54 mm)
signal-integrity model 74F652SPC
pins: 1 CLKAB (in), 2 SAB (in), 3 OEAB (in), 4 A0 (io), 5 A1 (io), 6 A2 (io), 7 A3 (io), 8 A4 (io), 9 A5 (io), 10 A6 (io), 11 A7 (io), 12 GND (power), 13 B7 (io), 14 B6 (io), 15 B5 (io), 16 B4 (io), 17 B3 (io), 18 B2 (io), 19 B1 (io), 20 B0 (io), 21 ~{OEBA} (in), 22 SBA (in), 23 CLKBA (in), 24 VCC (power)

## 74F2645SC
designator U?
Octal Bus Transceiver with 25W Series Resistor in the Output
footprint M20B_N (SOIC, 20-Leads, Body 12.8x7.5mm, Pitch 1.27mm, IPC Medium Density)
footprint M20B_L (SOIC, 20-Leads, Body 12.8x7.5mm, Pitch 1.27mm, IPC High Density)
footprint M20B_M (SOIC, 20-Leads, Body 12.8x7.5mm, Pitch 1.27mm, IPC Low Density)
3D model M20B (20-Pin Small Outline Integrated Circuit 1.27 mm Pitch)
signal-integrity model 74F2645SC
pins: 1 T/~{R} (in), 2 A0 (io), 3 A1 (io), 4 A2 (io), 5 A3 (io), 6 A4 (io), 7 A5 (io), 8 A6 (io), 9 A7 (io), 10 GND (power), 11 B7 (io), 12 B6 (io), 13 B5 (io), 14 B4 (io), 15 B3 (io), 16 B2 (io), 17 B1 (io), 18 B0 (io), 19 ~{OE} (in), 20 VCC (power)

## DM54LS245J
designator U?
3-State Octal Bus Transceiver
footprint J20A (DIP; 20 Leads; Row Spacing 7.62 mm; Pitch 2.54 mm)
3D model J20A (DIP; 20 Leads; Row Spacing 7.62 mm; Pitch 2.54 mm)
simulation model 74F245 (SIMCODE)
signal-integrity model DM54LS245J
pins: 1 T/~{R} (in), 2 A0 (io), 3 A1 (io), 4 A2 (io), 5 A3 (io), 6 A4 (io), 7 A5 (io), 8 A6 (io), 9 A7 (io), 10 GND (power), 11 B7 (io), 12 B6 (io), 13 B5 (io), 14 B4 (io), 15 B3 (io), 16 B2 (io), 17 B1 (io), 18 B0 (io), 19 ~{OE} (in), 20 VCC (power)

## DM54LS245W
designator U?
3-State Octal Bus Transceiver
footprint W20A (DFP; 20 Leads; Body 13.7 x 7.2 mm (LxW max); Pitch 1.27 mm)
3D model W20A (DFP; 20 Leads; Body 13.7 x 7.2 mm (LxW max); Pitch 1.27 mm)
simulation model 74F245 (SIMCODE)
signal-integrity model DM54LS245W
pins: 1 T/~{R} (in), 2 A0 (io), 3 A1 (io), 4 A2 (io), 5 A3 (io), 6 A4 (io), 7 A5 (io), 8 A6 (io), 9 A7 (io), 10 GND (power), 11 B7 (io), 12 B6 (io), 13 B5 (io), 14 B4 (io), 15 B3 (io), 16 B2 (io), 17 B1 (io), 18 B0 (io), 19 ~{OE} (in), 20 VCC (power)

## DM74ALS245ASJ
designator U?
Octal 3-State Bus Transceiver
footprint M20D_N (SOP, 20-Leads, Body 12.6x5.3mm, Pitch 1.27mm, IPC Medium Density)
footprint M20D_L (SOP, 20-Leads, Body 12.6x5.3mm, Pitch 1.27mm, IPC High Density)
footprint M20D_M (SOP, 20-Leads, Body 12.6x5.3mm, Pitch 1.27mm, IPC Low Density)
3D model M20D (20-Pin Small Outline Package 1.27 mm Pitch)
simulation model 74F245 (SIMCODE)
signal-integrity model DM74ALS245ASJ
pins: 1 T/~{R} (in), 2 A0 (io), 3 A1 (io), 4 A2 (io), 5 A3 (io), 6 A4 (io), 7 A5 (io), 8 A6 (io), 9 A7 (io), 10 GND (power), 11 B7 (io), 12 B6 (io), 13 B5 (io), 14 B4 (io), 15 B3 (io), 16 B2 (io), 17 B1 (io), 18 B0 (io), 19 ~{OE} (in), 20 VCC (power)

## DM74ALS245AWM
designator U?
Octal 3-State Bus Transceiver
footprint M20B_N (SOIC, 20-Leads, Body 12.8x7.5mm, Pitch 1.27mm, IPC Medium Density)
footprint M20B_L (SOIC, 20-Leads, Body 12.8x7.5mm, Pitch 1.27mm, IPC High Density)
footprint M20B_M (SOIC, 20-Leads, Body 12.8x7.5mm, Pitch 1.27mm, IPC Low Density)
3D model M20B (20-Pin Small Outline Integrated Circuit 1.27 mm Pitch)
simulation model 74F245 (SIMCODE)
signal-integrity model DM74ALS245AWM
pins: 1 T/~{R} (in), 2 A0 (io), 3 A1 (io), 4 A2 (io), 5 A3 (io), 6 A4 (io), 7 A5 (io), 8 A6 (io), 9 A7 (io), 10 GND (power), 11 B7 (io), 12 B6 (io), 13 B5 (io), 14 B4 (io), 15 B3 (io), 16 B2 (io), 17 B1 (io), 18 B0 (io), 19 ~{OE} (in), 20 VCC (power)

## DM74ALS245MSA
designator U?
Octal 3-State Bus Transceiver
footprint M20B_N (SOIC, 20-Leads, Body 12.8x7.5mm, Pitch 1.27mm, IPC Medium Density)
footprint M20B_L (SOIC, 20-Leads, Body 12.8x7.5mm, Pitch 1.27mm, IPC High Density)
footprint M20B_M (SOIC, 20-Leads, Body 12.8x7.5mm, Pitch 1.27mm, IPC Low Density)
3D model M20B (20-Pin Small Outline Integrated Circuit 1.27 mm Pitch)
simulation model 74F245 (SIMCODE)
signal-integrity model DM74ALS245MSA
pins: 1 T/~{R} (in), 2 A0 (io), 3 A1 (io), 4 A2 (io), 5 A3 (io), 6 A4 (io), 7 A5 (io), 8 A6 (io), 9 A7 (io), 10 GND (power), 11 B7 (io), 12 B6 (io), 13 B5 (io), 14 B4 (io), 15 B3 (io), 16 B2 (io), 17 B1 (io), 18 B0 (io), 19 ~{OE} (in), 20 VCC (power)

## DM74ALS640AN
designator U?
Inverting Octal Bus Transceiver
footprint N20A (DIP; 20 Leads; Row Spacing 7.62 mm; Pitch 2.54 mm)
3D model N20A (DIP; 20 Leads; Row Spacing 7.62 mm; Pitch 2.54 mm)
signal-integrity model DM74ALS640AN
pins: 1 T/~{R} (in), 2 A0 (io), 3 A1 (io), 4 A2 (io), 5 A3 (io), 6 A4 (io), 7 A5 (io), 8 A6 (io), 9 A7 (io), 10 GND (power), 11 B7 (io), 12 B6 (io), 13 B5 (io), 14 B4 (io), 15 B3 (io), 16 B2 (io), 17 B1 (io), 18 B0 (io), 19 ~{OE} (in), 20 VCC (power)

## DM74ALS640AWM
designator U?
Inverting Octal Bus Transceiver
footprint M20B_N (SOIC, 20-Leads, Body 12.8x7.5mm, Pitch 1.27mm, IPC Medium Density)
footprint M20B_L (SOIC, 20-Leads, Body 12.8x7.5mm, Pitch 1.27mm, IPC High Density)
footprint M20B_M (SOIC, 20-Leads, Body 12.8x7.5mm, Pitch 1.27mm, IPC Low Density)
3D model M20B (20-Pin Small Outline Integrated Circuit 1.27 mm Pitch)
signal-integrity model DM74ALS640AWM
pins: 1 T/~{R} (in), 2 A0 (io), 3 A1 (io), 4 A2 (io), 5 A3 (io), 6 A4 (io), 7 A5 (io), 8 A6 (io), 9 A7 (io), 10 GND (power), 11 B7 (io), 12 B6 (io), 13 B5 (io), 14 B4 (io), 15 B3 (io), 16 B2 (io), 17 B1 (io), 18 B0 (io), 19 ~{OE} (in), 20 VCC (power)

## DM74ALS645AN
designator U?
Octal Bus Transceiver
footprint N20A (DIP; 20 Leads; Row Spacing 7.62 mm; Pitch 2.54 mm)
3D model N20A (DIP; 20 Leads; Row Spacing 7.62 mm; Pitch 2.54 mm)
signal-integrity model DM74ALS645AN
pins: 1 DIR (in), 2 A1 (io), 3 A2 (io), 4 A3 (io), 5 A4 (io), 6 A5 (io), 7 A6 (io), 8 A7 (io), 9 A8 (io), 10 GND (power), 11 B8 (io), 12 B7 (io), 13 B6 (io), 14 B5 (io), 15 B4 (io), 16 B3 (io), 17 B2 (io), 18 B1 (io), 19 ~{OE} (in), 20 VCC (power)

## DM74ALS645AWM
designator U?
Octal Bus Transceiver
footprint M20B_N (SOIC, 20-Leads, Body 12.8x7.5mm, Pitch 1.27mm, IPC Medium Density)
footprint M20B_L (SOIC, 20-Leads, Body 12.8x7.5mm, Pitch 1.27mm, IPC High Density)
footprint M20B_M (SOIC, 20-Leads, Body 12.8x7.5mm, Pitch 1.27mm, IPC Low Density)
3D model M20B (20-Pin Small Outline Integrated Circuit 1.27 mm Pitch)
signal-integrity model DM74ALS645AWM
pins: 1 DIR (in), 2 A1 (io), 3 A2 (io), 4 A3 (io), 5 A4 (io), 6 A5 (io), 7 A6 (io), 8 A7 (io), 9 A8 (io), 10 GND (power), 11 B8 (io), 12 B7 (io), 13 B6 (io), 14 B5 (io), 15 B4 (io), 16 B3 (io), 17 B2 (io), 18 B1 (io), 19 ~{OE} (in), 20 VCC (power)

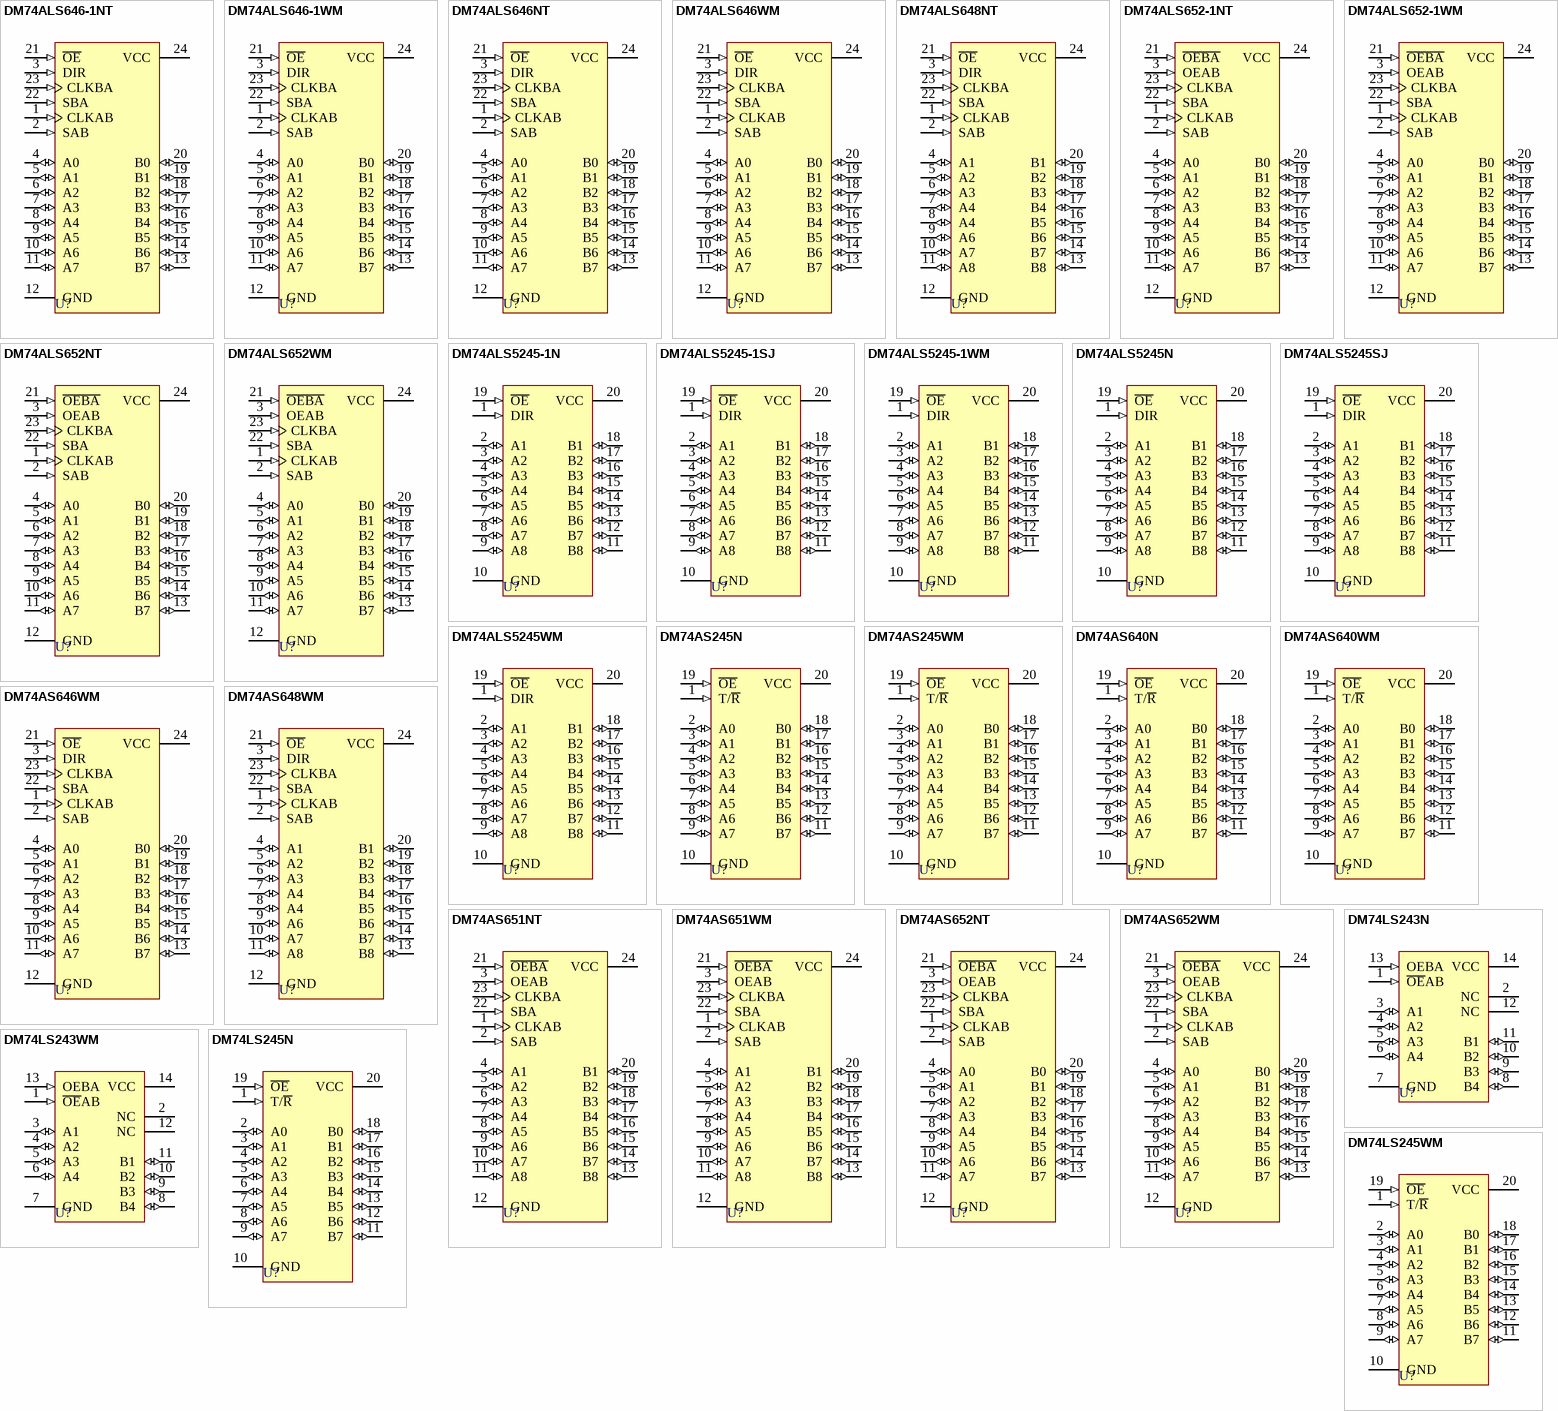
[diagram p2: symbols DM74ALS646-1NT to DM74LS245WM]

## DM74ALS646-1NT
designator U?
Octal 3-State Bus Transceiver and Register
footprint N24C (DIP; 24 Leads; Row Spacing 7.62 mm; Pitch 2.54 mm)
3D model N24C (DIP; 24 Leads; Row Spacing 7.62 mm; Pitch 2.54 mm)
signal-integrity model DM74ALS646-1NT
pins: 1 CLKAB (in), 2 SAB (in), 3 DIR (in), 4 A0 (io), 5 A1 (io), 6 A2 (io), 7 A3 (io), 8 A4 (io), 9 A5 (io), 10 A6 (io), 11 A7 (io), 12 GND (power), 13 B7 (io), 14 B6 (io), 15 B5 (io), 16 B4 (io), 17 B3 (io), 18 B2 (io), 19 B1 (io), 20 B0 (io), 21 ~{OE} (in), 22 SBA (in), 23 CLKBA (in), 24 VCC (power)

## DM74ALS646-1WM
designator U?
Octal 3-State Bus Transceiver and Register
footprint M24B_N (SOIC, 24-Leads, Body 15.4x7.5mm, Pitch 1.27mm, IPC Medium Density)
footprint M24B_L (SOIC, 24-Leads, Body 15.4x7.5mm, Pitch 1.27mm, IPC High Density)
footprint M24B_M (SOIC, 24-Leads, Body 15.4x7.5mm, Pitch 1.27mm, IPC Low Density)
3D model M24B (24-Pin Small Outline Integrated Circuit 1.27 mm Pitch)
signal-integrity model DM74ALS646-1WM
pins: 1 CLKAB (in), 2 SAB (in), 3 DIR (in), 4 A0 (io), 5 A1 (io), 6 A2 (io), 7 A3 (io), 8 A4 (io), 9 A5 (io), 10 A6 (io), 11 A7 (io), 12 GND (power), 13 B7 (io), 14 B6 (io), 15 B5 (io), 16 B4 (io), 17 B3 (io), 18 B2 (io), 19 B1 (io), 20 B0 (io), 21 ~{OE} (in), 22 SBA (in), 23 CLKBA (in), 24 VCC (power)

## DM74ALS646NT
designator U?
Octal 3-State Bus Transceiver and Register
footprint N24C (DIP; 24 Leads; Row Spacing 7.62 mm; Pitch 2.54 mm)
3D model N24C (DIP; 24 Leads; Row Spacing 7.62 mm; Pitch 2.54 mm)
signal-integrity model DM74ALS646NT
pins: 1 CLKAB (in), 2 SAB (in), 3 DIR (in), 4 A0 (io), 5 A1 (io), 6 A2 (io), 7 A3 (io), 8 A4 (io), 9 A5 (io), 10 A6 (io), 11 A7 (io), 12 GND (power), 13 B7 (io), 14 B6 (io), 15 B5 (io), 16 B4 (io), 17 B3 (io), 18 B2 (io), 19 B1 (io), 20 B0 (io), 21 ~{OE} (in), 22 SBA (in), 23 CLKBA (in), 24 VCC (power)

## DM74ALS646WM
designator U?
Octal 3-State Bus Transceiver and Register
footprint M24B_N (SOIC, 24-Leads, Body 15.4x7.5mm, Pitch 1.27mm, IPC Medium Density)
footprint M24B_L (SOIC, 24-Leads, Body 15.4x7.5mm, Pitch 1.27mm, IPC High Density)
footprint M24B_M (SOIC, 24-Leads, Body 15.4x7.5mm, Pitch 1.27mm, IPC Low Density)
3D model M24B (24-Pin Small Outline Integrated Circuit 1.27 mm Pitch)
signal-integrity model DM74ALS646WM
pins: 1 CLKAB (in), 2 SAB (in), 3 DIR (in), 4 A0 (io), 5 A1 (io), 6 A2 (io), 7 A3 (io), 8 A4 (io), 9 A5 (io), 10 A6 (io), 11 A7 (io), 12 GND (power), 13 B7 (io), 14 B6 (io), 15 B5 (io), 16 B4 (io), 17 B3 (io), 18 B2 (io), 19 B1 (io), 20 B0 (io), 21 ~{OE} (in), 22 SBA (in), 23 CLKBA (in), 24 VCC (power)

## DM74ALS648NT
designator U?
Octal Bus Transceiver and Register
footprint N24C (DIP; 24 Leads; Row Spacing 7.62 mm; Pitch 2.54 mm)
3D model N24C (DIP; 24 Leads; Row Spacing 7.62 mm; Pitch 2.54 mm)
signal-integrity model DM74ALS648NT
pins: 1 CLKAB (in), 2 SAB (in), 3 DIR (in), 4 A1 (io), 5 A2 (io), 6 A3 (io), 7 A4 (io), 8 A4 (io), 9 A6 (io), 10 A7 (io), 11 A8 (io), 12 GND (power), 13 B8 (io), 14 B7 (io), 15 B6 (io), 16 B5 (io), 17 B4 (io), 18 B3 (io), 19 B2 (io), 20 B1 (io), 21 ~{OE} (in), 22 SBA (in), 23 CLKBA (in), 24 VCC (power)

## DM74ALS652-1NT
designator U?
Octal 3-State Bus Transceiver and Register
footprint N24C (DIP; 24 Leads; Row Spacing 7.62 mm; Pitch 2.54 mm)
3D model N24C (DIP; 24 Leads; Row Spacing 7.62 mm; Pitch 2.54 mm)
signal-integrity model DM74ALS652-1NT
pins: 1 CLKAB (in), 2 SAB (in), 3 OEAB (in), 4 A0 (io), 5 A1 (io), 6 A2 (io), 7 A3 (io), 8 A4 (io), 9 A5 (io), 10 A6 (io), 11 A7 (io), 12 GND (power), 13 B7 (io), 14 B6 (io), 15 B5 (io), 16 B4 (io), 17 B3 (io), 18 B2 (io), 19 B1 (io), 20 B0 (io), 21 ~{OEBA} (in), 22 SBA (in), 23 CLKBA (in), 24 VCC (power)

## DM74ALS652-1WM
designator U?
Octal 3-State Bus Transceiver and Register
footprint M24B_N (SOIC, 24-Leads, Body 15.4x7.5mm, Pitch 1.27mm, IPC Medium Density)
footprint M24B_L (SOIC, 24-Leads, Body 15.4x7.5mm, Pitch 1.27mm, IPC High Density)
footprint M24B_M (SOIC, 24-Leads, Body 15.4x7.5mm, Pitch 1.27mm, IPC Low Density)
3D model M24B (24-Pin Small Outline Integrated Circuit 1.27 mm Pitch)
signal-integrity model DM74ALS652-1WM
pins: 1 CLKAB (in), 2 SAB (in), 3 OEAB (in), 4 A0 (io), 5 A1 (io), 6 A2 (io), 7 A3 (io), 8 A4 (io), 9 A5 (io), 10 A6 (io), 11 A7 (io), 12 GND (power), 13 B7 (io), 14 B6 (io), 15 B5 (io), 16 B4 (io), 17 B3 (io), 18 B2 (io), 19 B1 (io), 20 B0 (io), 21 ~{OEBA} (in), 22 SBA (in), 23 CLKBA (in), 24 VCC (power)

## DM74ALS652NT
designator U?
Octal 3-State Bus Transceiver and Register
footprint N24C (DIP; 24 Leads; Row Spacing 7.62 mm; Pitch 2.54 mm)
3D model N24C (DIP; 24 Leads; Row Spacing 7.62 mm; Pitch 2.54 mm)
signal-integrity model DM74ALS652NT
pins: 1 CLKAB (in), 2 SAB (in), 3 OEAB (in), 4 A0 (io), 5 A1 (io), 6 A2 (io), 7 A3 (io), 8 A4 (io), 9 A5 (io), 10 A6 (io), 11 A7 (io), 12 GND (power), 13 B7 (io), 14 B6 (io), 15 B5 (io), 16 B4 (io), 17 B3 (io), 18 B2 (io), 19 B1 (io), 20 B0 (io), 21 ~{OEBA} (in), 22 SBA (in), 23 CLKBA (in), 24 VCC (power)

## DM74ALS652WM
designator U?
Octal 3-State Bus Transceiver and Register
footprint M24B_N (SOIC, 24-Leads, Body 15.4x7.5mm, Pitch 1.27mm, IPC Medium Density)
footprint M24B_L (SOIC, 24-Leads, Body 15.4x7.5mm, Pitch 1.27mm, IPC High Density)
footprint M24B_M (SOIC, 24-Leads, Body 15.4x7.5mm, Pitch 1.27mm, IPC Low Density)
3D model M24B (24-Pin Small Outline Integrated Circuit 1.27 mm Pitch)
signal-integrity model DM74ALS652WM
pins: 1 CLKAB (in), 2 SAB (in), 3 OEAB (in), 4 A0 (io), 5 A1 (io), 6 A2 (io), 7 A3 (io), 8 A4 (io), 9 A5 (io), 10 A6 (io), 11 A7 (io), 12 GND (power), 13 B7 (io), 14 B6 (io), 15 B5 (io), 16 B4 (io), 17 B3 (io), 18 B2 (io), 19 B1 (io), 20 B0 (io), 21 ~{OEBA} (in), 22 SBA (in), 23 CLKBA (in), 24 VCC (power)

## DM74ALS5245-1N
designator U?
Octal 3-State Transceiver
footprint N20A (DIP; 20 Leads; Row Spacing 7.62 mm; Pitch 2.54 mm)
3D model N20A (DIP; 20 Leads; Row Spacing 7.62 mm; Pitch 2.54 mm)
simulation model 74F245 (SIMCODE)
signal-integrity model DM74ALS5245-1N
pins: 1 DIR (in), 2 A1 (io), 3 A2 (io), 4 A3 (io), 5 A4 (io), 6 A5 (io), 7 A6 (io), 8 A7 (io), 9 A8 (io), 10 GND (power), 11 B8 (io), 12 B7 (io), 13 B6 (io), 14 B5 (io), 15 B4 (io), 16 B3 (io), 17 B2 (io), 18 B1 (io), 19 ~{OE} (in), 20 VCC (power)

## DM74ALS5245-1SJ
designator U?
Octal 3-State Transceiver
footprint M20D_N (SOP, 20-Leads, Body 12.6x5.3mm, Pitch 1.27mm, IPC Medium Density)
footprint M20D_L (SOP, 20-Leads, Body 12.6x5.3mm, Pitch 1.27mm, IPC High Density)
footprint M20D_M (SOP, 20-Leads, Body 12.6x5.3mm, Pitch 1.27mm, IPC Low Density)
3D model M20D (20-Pin Small Outline Package 1.27 mm Pitch)
simulation model 74F245 (SIMCODE)
signal-integrity model DM74ALS5245-1SJ
pins: 1 DIR (in), 2 A1 (io), 3 A2 (io), 4 A3 (io), 5 A4 (io), 6 A5 (io), 7 A6 (io), 8 A7 (io), 9 A8 (io), 10 GND (power), 11 B8 (io), 12 B7 (io), 13 B6 (io), 14 B5 (io), 15 B4 (io), 16 B3 (io), 17 B2 (io), 18 B1 (io), 19 ~{OE} (in), 20 VCC (power)

## DM74ALS5245-1WM
designator U?
Octal 3-State Transceiver
footprint M20B_N (SOIC, 20-Leads, Body 12.8x7.5mm, Pitch 1.27mm, IPC Medium Density)
footprint M20B_L (SOIC, 20-Leads, Body 12.8x7.5mm, Pitch 1.27mm, IPC High Density)
footprint M20B_M (SOIC, 20-Leads, Body 12.8x7.5mm, Pitch 1.27mm, IPC Low Density)
3D model M20B (20-Pin Small Outline Integrated Circuit 1.27 mm Pitch)
simulation model 74F245 (SIMCODE)
signal-integrity model DM74ALS5245-1WM
pins: 1 DIR (in), 2 A1 (io), 3 A2 (io), 4 A3 (io), 5 A4 (io), 6 A5 (io), 7 A6 (io), 8 A7 (io), 9 A8 (io), 10 GND (power), 11 B8 (io), 12 B7 (io), 13 B6 (io), 14 B5 (io), 15 B4 (io), 16 B3 (io), 17 B2 (io), 18 B1 (io), 19 ~{OE} (in), 20 VCC (power)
